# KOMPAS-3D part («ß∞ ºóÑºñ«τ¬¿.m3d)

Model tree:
1. Эскиз:1
2. Операция выдавливания:1
     Расстояние 1 = 10; Расстояние 2 = 8.2
3. Эскиз:2
4. Операция выдавливания:2
     Расстояние 1 = 12; Расстояние 2 = 8.2
5. Условное изображение резьбы:1
     Длина резьбы = 2; Шаг резьбы = 1; Номинальный диаметр резьбы = 5
6. Эскиз:3
7. Операция выдавливания:3
     Расстояние 1 = 13.5; Расстояние 2 = 8.2
8. Эскиз:4
9. Операция выдавливания:4
     Расстояние 1 = 17.3; Расстояние 2 = 8.2
10. Эскиз:5
11. Операция выдавливания:5
     Расстояние 1 = 2; Расстояние 2 = 8.2
12. Условное изображение резьбы:2
     Длина резьбы = 2; Шаг резьбы = 1; Номинальный диаметр резьбы = 5
